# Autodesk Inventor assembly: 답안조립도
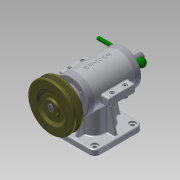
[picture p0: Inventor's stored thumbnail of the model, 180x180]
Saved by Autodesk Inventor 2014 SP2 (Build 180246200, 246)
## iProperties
Created: 2015-12
Part Number: 답안조립도
Document SubType Name: Assembly
Designer: Administrator
Mass: 1960.68 g
Surface Area: 1487.16 cm^2
Volume: 472.462 cm^3
Density: 4.14992 g/cm^3
Author: Administrator
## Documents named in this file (19)
- C:\Users\Administrator\Desktop\351207V1007\답안조립도.iam
- C:\Users\Administrator\Desktop\351207V1007\본체.ipt
- C:\Users\Administrator\Desktop\351207V1007\베어링 6202.ipt
- C:\Users\Administrator\Desktop\351207V1007\키 4 x 4 x 18.ipt
- C:\Users\Administrator\Desktop\351207V1007\편심축.ipt
- C:\Users\Administrator\Desktop\351207V1007\앞커버.ipt
- C:\Users\Administrator\Desktop\351207V1007\오일실 12 22 7.ipt
- C:\Users\Administrator\Desktop\351207V1007\뒤커버.ipt
- C:\Users\Administrator\Desktop\351207V1007\베어링 6201.ipt
- C:\Users\Administrator\Desktop\351207V1007\스프링.ipt
- C:\Users\Administrator\Desktop\351207V1007\슬라이드.ipt
- C:\Users\Administrator\Desktop\351207V1007\본체커버.ipt
- C:\Users\Administrator\Desktop\351207V1007\볼트 M3x0.5x8.ipt
- C:\Users\Administrator\Desktop\351207V1007\V-벨트풀리.ipt
- C:\Users\Administrator\Desktop\351207V1007\멈춤나사 M3x8.ipt
- C:\Users\Administrator\Desktop\351207V1007\볼트 M4 x 16.ipt
- C:\Users\Administrator\Desktop\351207V1007\너트 M4.ipt
- C:\Users\Administrator\Desktop\351207V1007\와셔 ST 4-100.ipt
- C:\Users\Administrator\Desktop\351207V1007\레바.ipt
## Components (13 placed, 4 different names)
1. V-벨트풀리:1
2. ISO 4762 M4 x 16:1
3. ISO 4762 M4 x 16:2
4. ISO 4762 M4 x 16:3
5. ISO 4762 M4 x 16:4
6. ISO 4032 M4:1
7. ISO 7091 ST 4 - 100 HV:1
8. ISO 4032 M4:2
9. ISO 7091 ST 4 - 100 HV:2
10. ISO 4032 M4:3
11. ISO 7091 ST 4 - 100 HV:3
12. ISO 4032 M4:4
13. ISO 7091 ST 4 - 100 HV:4
